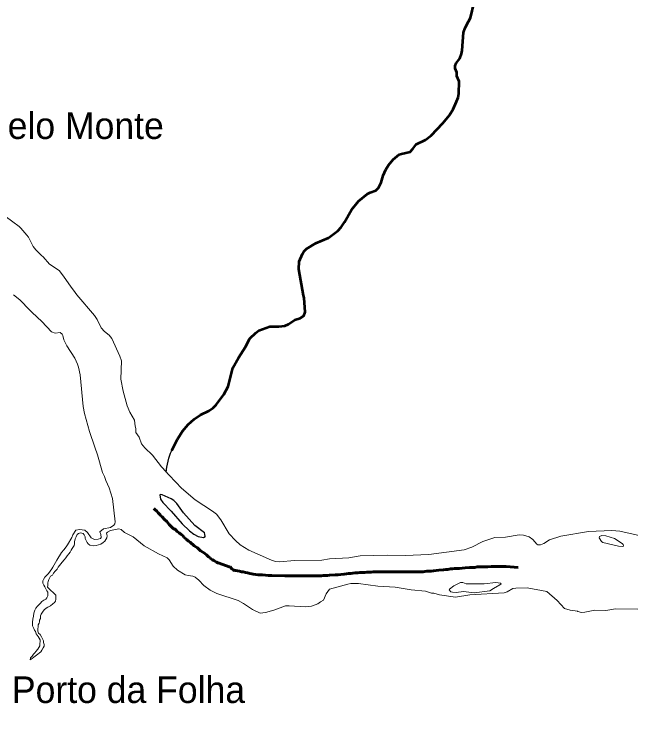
# Model space of a CAD drawing. Extents: x -1643653 to 4543381, y 1624270 to 13878484.
# Drawn here: x 689766 to 701363, y 8902478 to 8915829 of the extents above; entities that cross this region are included whole.
import ezdxf

# ---------------------------------------------------------------- set-up
doc = ezdxf.new("R2010")
doc.units = 0
doc.header["$LTSCALE"] = 200
doc.linetypes.add('LONG_DASH_SHORT_DASH', pattern=[9.9, 6, -1.2, 1.5, -1.2])
for name, color, linetype, lineweight in [('23', 7, 'Continuous', 13), ('24', 7, 'Continuous', 25), ('25', 7, 'Continuous', 13), ('60', 7, 'Continuous', 13), ('7', 7, 'LONG_DASH_SHORT_DASH', 60)]:
    doc.layers.add(name, color=color, linetype=linetype, lineweight=lineweight)
doc.layers.add('41', color=7, linetype='Continuous')

msp = doc.modelspace()

# ---------------------------------------------------------------- linework, layer by layer
at = {"layer": '23'}
for points in [[(689858, 8911832.1), (689622.7, 8912010.6), (689578.8, 8912037.9)], [(689858, 8911832.1), (689622.7, 8912010.6), (689578.8, 8912037.9)], [(690003.7, 8911671.2), (689891.4, 8911806.7), (689858, 8911832.1)], [(690003.7, 8911671.2), (689891.4, 8911806.7), (689858, 8911832.1)], [(690282.6, 8911287.6), (690170.1, 8911393.1), (690124.3, 8911459.3), (690036.2, 8911631.9), (690003.7, 8911671.2)], [(690282.6, 8911287.6), (690170.1, 8911393.1), (690124.3, 8911459.3), (690036.2, 8911631.9), (690003.7, 8911671.2)], [(690884, 8910634.6), (690838.4, 8910691.9), (690695.1, 8910901.9), (690608.8, 8911006.4), (690430.8, 8911126.3), (690310.1, 8911261.8), (690282.6, 8911287.6)], [(690884, 8910634.6), (690838.4, 8910691.9), (690695.1, 8910901.9), (690608.8, 8911006.4), (690430.8, 8911126.3), (690310.1, 8911261.8), (690282.6, 8911287.6)], [(692044.8, 8908056.7), (692038.9, 8908078.6), (692026.3, 8908188.9), (691941, 8908340.7), (691889.9, 8908460.7), (691815.3, 8908738.4), (691774.2, 8908959.6), (691782, 8909306.7), (691754.7, 8909393.1), (691600.1, 8909727.4), (691549.6, 8909789.6), (691461.9, 8909862.4), (691401.2, 8909927.1), (691329, 8910084.3), (691277.7, 8910162.7), (690943.9, 8910550.7), (690884, 8910634.6)], [(692044.8, 8908056.7), (692038.9, 8908078.6), (692026.3, 8908188.9), (691941, 8908340.7), (691889.9, 8908460.7), (691815.3, 8908738.4), (691774.2, 8908959.6), (691782, 8909306.7), (691754.7, 8909393.1), (691600.1, 8909727.4), (691549.6, 8909789.6), (691461.9, 8909862.4), (691401.2, 8909927.1), (691329, 8910084.3), (691277.7, 8910162.7), (690943.9, 8910550.7), (690884, 8910634.6)], [(692676.4, 8907162.1), (692551.5, 8907299.7), (692534.1, 8907312.8), (692364.9, 8907535.6), (692220.3, 8907669.3), (692160.1, 8907748.4), (692118.3, 8907868.3), (692050.7, 8907961), (692052.8, 8908026.7), (692044.8, 8908056.7)], [(692676.4, 8907162.1), (692551.5, 8907299.7), (692534.1, 8907312.8), (692364.9, 8907535.6), (692220.3, 8907669.3), (692160.1, 8907748.4), (692118.3, 8907868.3), (692050.7, 8907961), (692052.8, 8908026.7), (692044.8, 8908056.7)], [(699730.1, 8905870.1), (699662.2, 8905846.3), (699617, 8905846.3), (699595.2, 8905855.7), (699522.1, 8905946.6), (699449.5, 8905993.7), (699343.2, 8906026.8), (699263.6, 8906033.6), (699008.1, 8905992.8), (698805.8, 8905980.6), (698581.3, 8905906.7), (698370.6, 8905800.9), (698229, 8905748.8), (697567.1, 8905664.3), (697116.6, 8905647.9), (696786.4, 8905651), (696272.7, 8905636.6), (696059.6, 8905599.2), (695698.2, 8905581.4), (695553.9, 8905557.9), (695038, 8905553.4), (694755.6, 8905527.6), (694682.1, 8905531.8), (694607.4, 8905554.6), (694182.1, 8905744), (694016.8, 8905845.3), (693928.4, 8905925.4), (693809.1, 8906055.6), (693809.1, 8906055.6), (693650.4, 8906314.4), (693569.9, 8906419.6), (693492.8, 8906479), (693169.8, 8906693.4), (692915.7, 8906912.1), (692807.4, 8907022.5), (692676.4, 8907162.1)], [(699730.1, 8905870.1), (699662.2, 8905846.3), (699617, 8905846.3), (699595.2, 8905855.7), (699522.1, 8905946.6), (699449.5, 8905993.7), (699343.2, 8906026.8), (699263.6, 8906033.6), (699008.1, 8905992.8), (698805.8, 8905980.6), (698581.3, 8905906.7), (698370.6, 8905800.9), (698229, 8905748.8), (697567.1, 8905664.3), (697116.6, 8905647.9), (696786.4, 8905651), (696272.7, 8905636.6), (696059.6, 8905599.2), (695698.2, 8905581.4), (695553.9, 8905557.9), (695038, 8905553.4), (694755.6, 8905527.6), (694682.1, 8905531.8), (694607.4, 8905554.6), (694182.1, 8905744), (694016.8, 8905845.3), (693928.4, 8905925.4), (693809.1, 8906055.6), (693809.1, 8906055.6), (693650.4, 8906314.4), (693569.9, 8906419.6), (693492.8, 8906479), (693169.8, 8906693.4), (692915.7, 8906912.1), (692807.4, 8907022.5), (692676.4, 8907162.1)], [(703043.5, 8905742.3), (702942.6, 8905799.8), (702682, 8905912.8), (702436.8, 8905905.5), (702373, 8905910.6), (702175.9, 8905983.8), (702058.9, 8906003.4), (701803.5, 8905986.5), (701659.8, 8905992.8), (701154.5, 8906101.4), (701005.2, 8906113.6), (700564.9, 8906093.9), (700049.1, 8906011), (699833.6, 8905937.4), (699730.1, 8905870.1)], [(703043.5, 8905742.3), (702942.6, 8905799.8), (702682, 8905912.8), (702436.8, 8905905.5), (702373, 8905910.6), (702175.9, 8905983.8), (702058.9, 8906003.4), (701803.5, 8905986.5), (701659.8, 8905992.8), (701154.5, 8906101.4), (701005.2, 8906113.6), (700564.9, 8906093.9), (700049.1, 8906011), (699833.6, 8905937.4), (699730.1, 8905870.1)]]:
    msp.add_lwpolyline(points, dxfattribs=at)
at = {"layer": '24', "lineweight": 53}
for points in [[(698310.3, 8915692), (698345.2, 8915759.1), (698414.2, 8916049.1), (698434, 8916103.3), (698493.2, 8916205.4), (698541, 8916255.4), (698604.5, 8916300.2), (698689, 8916338.6), (698872.4, 8916392.4), (698958.8, 8916447.6), (698989, 8916484.6), (699031.1, 8916558.4), (699106, 8916749.2)], [(698089.5, 8914668.2), (698093, 8914730.9), (698057.9, 8914805.5), (698057.7, 8914860.2), (698080.5, 8914908.2), (698146.1, 8914998.1), (698179.3, 8915082.2), (698193.2, 8915143.2), (698213.4, 8915483.8), (698249.4, 8915574.9), (698249.4, 8915574.9), (698310.3, 8915692)], [(697317.1, 8913373.6), (697317.9, 8913374.9), (697500, 8913466.1), (697607.5, 8913547.4), (697828, 8913780.1), (697955.3, 8913931.9), (698021, 8914043.8), (698087.2, 8914183.8), (698114.2, 8914261.7), (698128.6, 8914336.6), (698136.1, 8914565.5), (698089.3, 8914664.5), (698089.5, 8914668.2)], [(695208.7, 8910534.7), (695119.1, 8911032.8), (695125.9, 8911175.9), (695186, 8911322.3), (695215, 8911364.1), (695265.4, 8911414.9), (695441.6, 8911520.3), (695675, 8911623.5), (695855.8, 8911754), (695917.1, 8911825.5), (695978.8, 8911914.3), (696107.7, 8912146.4), (696241.4, 8912314.4), (696408, 8912448.3), (696458.2, 8912475.5), (696564.9, 8912514.1), (696620.1, 8912562.5), (696669.6, 8912662.3), (696705.8, 8912792.2), (696757.7, 8912906), (696806.1, 8912989), (696891.2, 8913095.4), (697004, 8913188.5), (697047.8, 8913204.1), (697212.1, 8913236.8), (697263.3, 8913295.3), (697317.1, 8913373.6)], [(692729.3, 8907617.7), (692837, 8907833), (692931.9, 8907984.6), (693036.8, 8908107.6), (693151.9, 8908211.5), (693272.4, 8908290), (693424.2, 8908367.8), (693510.8, 8908421.2), (693567.8, 8908481.1), (693707.6, 8908675), (693789, 8908827.4), (693880.7, 8909177.6), (693984.3, 8909363.3), (694118.8, 8909572.9), (694196.2, 8909725.9), (694310.5, 8909836.8), (694368.1, 8909876.1), (694574.8, 8909952.9), (694743.6, 8909954), (694858.1, 8909968.9), (694926.1, 8910000.5), (695042.3, 8910075.9), (695142.1, 8910109.8), (695197.6, 8910138.8), (695213.4, 8910155.1), (695235.8, 8910220.2), (695216.8, 8910490.1), (695208.7, 8910534.7)]]:
    msp.add_lwpolyline(points, dxfattribs=at)
at = {"layer": '24'}
for points in [[(698310.3, 8915692), (698345.2, 8915759.1), (698414.2, 8916049.1), (698434, 8916103.3), (698493.2, 8916205.4), (698541, 8916255.4), (698604.5, 8916300.2), (698689, 8916338.6), (698872.4, 8916392.4), (698958.8, 8916447.6), (698989, 8916484.6), (699031.1, 8916558.4), (699106, 8916749.2)], [(698089.5, 8914668.2), (698093, 8914730.9), (698057.9, 8914805.5), (698057.7, 8914860.2), (698080.5, 8914908.2), (698146.1, 8914998.1), (698179.3, 8915082.2), (698193.2, 8915143.2), (698213.4, 8915483.8), (698249.4, 8915574.9), (698249.4, 8915574.9), (698310.3, 8915692)], [(697317.1, 8913373.6), (697317.9, 8913374.9), (697500, 8913466.1), (697607.5, 8913547.4), (697828, 8913780.1), (697955.3, 8913931.9), (698021, 8914043.8), (698087.2, 8914183.8), (698114.2, 8914261.7), (698128.6, 8914336.6), (698136.1, 8914565.5), (698089.3, 8914664.5), (698089.5, 8914668.2)], [(695208.7, 8910534.7), (695119.1, 8911032.8), (695125.9, 8911175.9), (695186, 8911322.3), (695215, 8911364.1), (695265.4, 8911414.9), (695441.6, 8911520.3), (695675, 8911623.5), (695855.8, 8911754), (695917.1, 8911825.5), (695978.8, 8911914.3), (696107.7, 8912146.4), (696241.4, 8912314.4), (696408, 8912448.3), (696458.2, 8912475.5), (696564.9, 8912514.1), (696620.1, 8912562.5), (696669.6, 8912662.3), (696705.8, 8912792.2), (696757.7, 8912906), (696806.1, 8912989), (696891.2, 8913095.4), (697004, 8913188.5), (697047.8, 8913204.1), (697212.1, 8913236.8), (697263.3, 8913295.3), (697317.1, 8913373.6)], [(692627.4, 8907216), (692639.9, 8907309.9), (692674.3, 8907477.3), (692707.2, 8907573.5), (692837, 8907833), (692931.9, 8907984.6), (693036.8, 8908107.6), (693151.9, 8908211.5), (693272.4, 8908290), (693424.2, 8908367.8), (693510.8, 8908421.2), (693567.8, 8908481.1), (693707.6, 8908675), (693789, 8908827.4), (693880.7, 8909177.6), (693984.3, 8909363.3), (694118.8, 8909572.9), (694196.2, 8909725.9), (694310.5, 8909836.8), (694368.1, 8909876.1), (694574.8, 8909952.9), (694743.6, 8909954), (694858.1, 8909968.9), (694926.1, 8910000.5), (695042.3, 8910075.9), (695142.1, 8910109.8), (695197.6, 8910138.8), (695213.4, 8910155.1), (695235.8, 8910220.2), (695216.8, 8910490.1), (695208.7, 8910534.7)]]:
    msp.add_lwpolyline(points, dxfattribs=at)
msp.add_lwpolyline([(692949.1, 8906444.8), (692825.9, 8906621.7), (692768.5, 8906681.2), (692716.6, 8906713.2), (692549.3, 8906785.2), (692516.7, 8906791.5), (692502.1, 8906785.4), (692518.4, 8906705.4), (692562.6, 8906642), (692720.7, 8906481.3), (692924.1, 8906239.9), (693063.6, 8906110.7), (693147.4, 8906045), (693227.3, 8906002.2), (693327.7, 8905986.2), (693357, 8906001.2), (693353.1, 8906048.7), (693342.8, 8906070), (693166.4, 8906209.1)], close=True, dxfattribs=at)
at = {"layer": '25'}
for points in [[(689578.8, 8912037.9), (689622.7, 8912010.6), (689858, 8911832.1)], [(689858, 8911832.1), (689891.4, 8911806.7), (690003.7, 8911671.2)], [(690003.7, 8911671.2), (690036.2, 8911631.9), (690124.3, 8911459.3), (690170.1, 8911393.1), (690282.6, 8911287.6)], [(690282.6, 8911287.6), (690310.1, 8911261.8), (690430.8, 8911126.3), (690608.8, 8911006.4), (690695.1, 8910901.9), (690838.4, 8910691.9), (690884, 8910634.6)], [(690884, 8910634.6), (690943.9, 8910550.7), (691277.7, 8910162.7), (691329, 8910084.3), (691401.2, 8909927.1), (691461.9, 8909862.4), (691549.6, 8909789.6), (691600.1, 8909727.4), (691754.7, 8909393.1), (691782, 8909306.7), (691774.2, 8908959.6), (691815.3, 8908738.4), (691889.9, 8908460.7), (691941, 8908340.7), (692026.3, 8908188.9), (692038.9, 8908078.6), (692044.8, 8908056.7)], [(690105.8, 8910215.6), (690059.9, 8910258.2), (689871, 8910454.6), (689754.4, 8910550.3)], [(690973.8, 8909186.5), (690959.4, 8909246.9), (690907.6, 8909357.3), (690755.8, 8909591), (690701.9, 8909701.7), (690681.3, 8909786.2), (690666.4, 8909810.3), (690629.5, 8909837.9), (690534.7, 8909826.2), (690465.2, 8909853.3), (690285, 8910049.6), (690105.8, 8910215.6)], [(691088.5, 8908313.9), (691062.8, 8908449.1), (691008.4, 8909041.9), (690973.8, 8909186.5)], [(691281.4, 8907685.4), (691182.4, 8907975.5), (691088.5, 8908313.9)], [(692044.8, 8908056.7), (692052.8, 8908026.7), (692050.7, 8907961), (692118.3, 8907868.3), (692160.1, 8907748.4), (692220.3, 8907669.3), (692364.9, 8907535.6), (692534.1, 8907312.8), (692551.5, 8907299.7), (692676.4, 8907162.1)], [(691462.3, 8907129.9), (691427, 8907209), (691331.2, 8907539.4), (691281.4, 8907685.4)], [(690770.2, 8905843.2), (690852, 8905982.1), (690868.1, 8906034.4), (690928, 8906123.4), (690992.1, 8906133.5), (691093.1, 8906124.6), (691142.8, 8906079.2), (691216.8, 8905979), (691277.6, 8905948.2), (691342.5, 8905951.8), (691386.5, 8905966.2), (691399.8, 8905981.8), (691397.7, 8906042.2), (691378.7, 8906092.7), (691448.3, 8906144.9), (691574.6, 8906171.9), (691637.5, 8906214.2), (691659.8, 8906239.5), (691666.5, 8906276.9), (691614.3, 8906720.4), (691553.2, 8906917.7), (691488.1, 8907058.8), (691462.3, 8907129.9)], [(692676.4, 8907162.1), (692807.4, 8907022.5), (692915.7, 8906912.1), (693169.8, 8906693.4), (693492.8, 8906479), (693569.9, 8906419.6), (693650.4, 8906314.4), (693809.1, 8906055.6), (693809.1, 8906055.6), (693928.4, 8905925.4), (694016.8, 8905845.3), (694182.1, 8905744), (694607.4, 8905554.6), (694682.1, 8905531.8), (694755.6, 8905527.6), (695038, 8905553.4), (695553.9, 8905557.9), (695698.2, 8905581.4), (696059.6, 8905599.2), (696272.7, 8905636.6), (696786.4, 8905651), (697116.6, 8905647.9), (697567.1, 8905664.3), (698229, 8905748.8), (698370.6, 8905800.9), (698581.3, 8905906.7), (698805.8, 8905980.6), (699008.1, 8905992.8), (699263.6, 8906033.6), (699343.2, 8906026.8), (699449.5, 8905993.7), (699522.1, 8905946.6), (699595.2, 8905855.7), (699617, 8905846.3), (699662.2, 8905846.3), (699730.1, 8905870.1)], [(691259.2, 8905826.4), (691259.2, 8905826.4), (691190.1, 8905839.8), (691158.9, 8905862.1), (691141.1, 8905891), (691121, 8905926.7), (691103.2, 8905962.3), (691098.7, 8905998), (691080.9, 8906031.4), (691063.1, 8906058.1), (691014, 8906069.2), (691014, 8906069.2), (690976.2, 8906058.1), (690976.2, 8906058.1), (690950.8, 8906042.4), (690932.7, 8905999.2), (690914.6, 8905958.6), (690901.5, 8905902.7), (690898.7, 8905862), (690893.5, 8905831.5), (690857.5, 8905778.3), (690836.9, 8905745.3), (690816.3, 8905709.8), (690790.7, 8905676.9), (690759.9, 8905638.9), (690736.8, 8905603.4), (690706, 8905562.8), (690670.1, 8905517.2), (690641.9, 8905486.9), (690618.8, 8905459), (690595.7, 8905428.6), (690575.1, 8905388), (690536.7, 8905350.1), (690503.4, 8905312.1), (690485.4, 8905276.6), (690449.6, 8905256.4), (690436.7, 8905228.5), (690418.7, 8905190.4), (690405.7, 8905157.4), (690397.9, 8905129.5), (690397.6, 8905081.1), (690392.3, 8905048.1), (690422.7, 8905017.4), (690453, 8904989.3), (690498.6, 8904945.8), (690526.4, 8904922.7), (690546.6, 8904897.2), (690546.1, 8904820.8), (690543.3, 8904787.8), (690525.4, 8904759.9), (690492.1, 8904737.2), (690446.1, 8904699.3), (690400.1, 8904671.6), (690366.9, 8904653.9), (690328.6, 8904623.6), (690300.3, 8904580.5), (690274.6, 8904539.9), (690261.7, 8904512), (690258.8, 8904461.2), (690240.8, 8904428.2), (690240.6, 8904397.7), (690232.8, 8904369.7), (690214.8, 8904339.3), (690214.6, 8904308.8), (690211.8, 8904260.4), (690211.5, 8904219.8), (690221.5, 8904181.5), (690251.8, 8904155.9), (690282.1, 8904117.6), (690297.2, 8904079.4), (690317.2, 8904038.6), (690319.6, 8904010.6), (690327, 8903972.4), (690326.8, 8903941.8), (690311.3, 8903908.9), (690288.2, 8903863.2), (690267.6, 8903835.3), (690239.5, 8903812.6), (690211.3, 8903787.3), (690183.2, 8903767.1), (690134.7, 8903731.8), (690106.5, 8903709), (690068.2, 8903683.8), (690073.5, 8903719.4), (690106.8, 8903752.2), (690129.9, 8903787.7), (690155.5, 8903813), (690176.1, 8903840.9), (690211.9, 8903881.4), (690230, 8903916.9), (690248, 8903947.4), (690250.8, 8903988), (690256.1, 8904026.2), (690256.3, 8904059.2), (690236.2, 8904089.9), (690218.5, 8904118), (690195.8, 8904146.1), (690180.7, 8904174.1), (690165.7, 8904212.4), (690148.1, 8904243), (690133, 8904273.6)], [(691574.8, 8906114.8), (691519.4, 8906081.7), (691502.8, 8906063.3), (691513.3, 8906012.8), (691511.5, 8905978.9), (691473.5, 8905914.1), (691441.2, 8905891.3)], [(694392.3, 8904560.9), (694249.3, 8904629.2), (694079.7, 8904743.6), (693976.2, 8904798), (693575.7, 8904930.8), (693449.1, 8904994.9), (693335.6, 8905079), (693236.3, 8905180.3), (693168.5, 8905236.3), (693127.6, 8905254.1), (693035.4, 8905267.9), (692983.1, 8905283.9), (692837.7, 8905367.1), (692753.6, 8905443.3), (692681.2, 8905561), (692642.1, 8905601), (692477.9, 8905674), (692207.4, 8905825.7), (692006.3, 8905995.8), (691843, 8906078.6), (691777.9, 8906135.4), (691733.2, 8906147.2), (691574.8, 8906114.8)], [(699730.1, 8905870.1), (699833.6, 8905937.4), (700049.1, 8906011), (700564.9, 8906093.9), (701005.2, 8906113.6), (701154.5, 8906101.4), (701659.8, 8905992.8), (701803.5, 8905986.5), (702058.9, 8906003.4), (702175.9, 8905983.8), (702373, 8905910.6), (702436.8, 8905905.5), (702682, 8905912.8), (702942.6, 8905799.8), (703043.5, 8905742.3)], [(690133, 8904273.6), (690112.9, 8904319.5), (690113.4, 8904393.3), (690118.8, 8904446.7), (690131.9, 8904502.6), (690134.8, 8904558.5), (690153, 8904614.4), (690171, 8904655), (690204.3, 8904690.4), (690235.1, 8904723.3), (690260.7, 8904751.2), (690283.8, 8904779), (690322.1, 8904801.7), (690360.4, 8904821.8), (690378.3, 8904849.7), (690396.4, 8904887.8), (690396.8, 8904953.9), (690381.7, 8904982), (690361.6, 8905017.7), (690341.5, 8905058.6), (690323.9, 8905086.6), (690306.3, 8905127.4), (690306.6, 8905168.1), (690314.4, 8905193.5), (690340.1, 8905236.6), (690373.4, 8905267), (690409.2, 8905307.5), (690440, 8905348), (690475.9, 8905391.1), (690494, 8905426.6), (690519.7, 8905469.7), (690566, 8905556), (690657.5, 8905699.5), (690657.5, 8905699.5), (690702.1, 8905750.7), (690702.1, 8905750.7), (690746.6, 8905810.9), (690770.2, 8905843.2)], [(691441.2, 8905891.3), (691395.3, 8905858.9), (691308.5, 8905834.7), (691259.2, 8905826.4)], [(697658.8, 8904933.3), (697614.4, 8904938.5), (697502.5, 8904976.8), (697230.9, 8904997.9), (696928.2, 8905046.6), (696603.4, 8905069), (696240.1, 8905118.1), (696100.1, 8905116.6), (696040.6, 8905107), (695698.7, 8905008.5), (695631.9, 8904924.3), (695580.3, 8904801.6), (695529.7, 8904770.2)], [(700224.1, 8904617.8), (700117.5, 8904650.2), (699976.3, 8904795.3), (699784.6, 8904967), (699413.2, 8905038.8), (699203.8, 8905030.7), (699146, 8905026.8), (699035.3, 8904960.2), (698980, 8904944.5), (698337.8, 8904907.7), (698063.3, 8904859.2), (697765.1, 8904905.4), (697658.8, 8904933.3)], [(695529.7, 8904770.2), (695479.1, 8904738.8), (695358.2, 8904694.2), (695244.6, 8904680.4), (694936.5, 8904701), (694868.4, 8904699.3), (694652.2, 8904617.7), (694490.8, 8904574.4), (694392.3, 8904560.9)], [(700368.5, 8904593.8), (700361.3, 8904595.9), (700224.1, 8904617.8)], [(701498, 8904635.9), (701073.3, 8904639.9), (700893.6, 8904612.2), (700683.7, 8904613.8), (700499, 8904578.5), (700435.5, 8904574.2), (700368.5, 8904593.8)]]:
    msp.add_lwpolyline(points, dxfattribs=at)
for points in [[(692949.1, 8906444.8), (692825.9, 8906621.7), (692768.5, 8906681.2), (692716.6, 8906713.2), (692549.3, 8906785.2), (692516.7, 8906791.5), (692502.1, 8906785.4), (692518.4, 8906705.4), (692562.6, 8906642), (692720.7, 8906481.3), (692924.1, 8906239.9), (693063.6, 8906110.7), (693147.4, 8906045), (693227.3, 8906002.2), (693327.7, 8905986.2), (693357, 8906001.2), (693353.1, 8906048.7), (693342.8, 8906070), (693166.4, 8906209.1)], [(700838.5, 8905891.3), (701132.3, 8905819.6), (701206.6, 8905813.1), (701222.7, 8905818.2), (701228.3, 8905829.3), (701220.6, 8905851.5), (701199.7, 8905872.4), (701053.6, 8905962.1), (700895.4, 8906014.9), (700818.6, 8906021.5), (700774.5, 8906004.3), (700770.3, 8905978.1), (700810.1, 8905908.9)], [(698388.1, 8905109.3), (698266.4, 8905115), (698201.6, 8905136.8), (698161, 8905135.9), (698032.8, 8905076.5), (697953.2, 8905013.6), (697944, 8904996.2), (697979.2, 8904962.2), (698006.7, 8904952.9), (698079.2, 8904948.8), (698215.6, 8904965.4), (698416.1, 8904942.8), (698710.2, 8904978.5), (698778.6, 8905025.1), (698900.2, 8905090.5), (698922.8, 8905112.6), (698909.9, 8905123.1), (698826.8, 8905137.9), (698603.2, 8905114.8)]]:
    msp.add_lwpolyline(points, close=True, dxfattribs=at)
at = {"layer": '60', "lineweight": 25}
msp.add_spline([(814781, 9009175.5), (814787.2, 9009173.4), (814796.9, 9009173.4), (814799.4, 9009172.4), (814805.1, 9009174.5), (814805.6, 9009176.5), (814811.7, 9009179.5), (814811.7, 9009179.5), (814801.5, 9009181), (814790.7, 9009181.5), (814784.1, 9009183.1), (814777.4, 9009185.1), (814778.4, 9009175.5)], degree=3, dxfattribs=at)
at = {"layer": '7'}
for points in [[(693130.7, 8905846.2), (693095, 8905876.9), (693074.7, 8905894.8), (693044.1, 8905912.6), (693023.8, 8905933.1), (693000.9, 8905948.4), (692983.1, 8905968.9), (692955.1, 8905989.3), (692934.7, 8906022.6), (692904.1, 8906037.9), (692871.1, 8906073.7), (692830.3, 8906094.1), (692797.2, 8906132.5), (692754, 8906155.5), (692713.2, 8906198.9), (692680.2, 8906229.6), (692634.3, 8906283.3), (692593.6, 8906324.2), (692550.3, 8906370.2), (692522.3, 8906390.6), (692509.6, 8906411.1), (692476.5, 8906446.9), (692448.5, 8906480.1), (692412.9, 8906510.8), (692392.5, 8906531.2)], [(694492.2, 8905273.6), (694436.2, 8905278.7), (694392.9, 8905278.7), (694352.2, 8905281.3), (694260.6, 8905294.1), (694235.2, 8905299.2), (694197, 8905306.9), (694176.7, 8905314.5), (694151.2, 8905319.6), (694115.6, 8905327.3), (694074.9, 8905335), (694044.3, 8905340.1), (694003.6, 8905347.8), (693965.4, 8905355.4), (693932.4, 8905360.5), (693912, 8905363.1), (693881.5, 8905373.3), (693861.1, 8905391.2), (693830.6, 8905429.6), (693810.2, 8905432.1), (693619.3, 8905498.6), (693596.4, 8905508.8), (693573.5, 8905521.6), (693553.2, 8905534.3), (693522.6, 8905552.2), (693494.6, 8905562.5), (693466.6, 8905580.3), (693448.8, 8905600.8), (693418.3, 8905618.7), (693382.7, 8905654.5), (693349.6, 8905685.2), (693324.1, 8905700.5), (693270.7, 8905733.7), (693240.1, 8905766.9), (693212.1, 8905787.4), (693153.6, 8905828.3), (693130.7, 8905846.2)], [(699241.8, 8905417.5), (699018.7, 8905439.9), (698972.9, 8905439.9), (698924.6, 8905439.9), (698871.2, 8905439.9), (698799.9, 8905439.9), (698733.8, 8905439.9), (698675.2, 8905434.8), (698609.1, 8905432.2), (698563.3, 8905432.2), (698520, 8905429.6), (698474.2, 8905429.6), (698431, 8905422), (698387.7, 8905422), (698331.7, 8905419.4), (698247.8, 8905411.7), (698191.8, 8905409.2), (698140.9, 8905401.5), (698092.6, 8905401.5), (698049.3, 8905399), (698008.6, 8905391.3), (697970.4, 8905391.3), (697922.1, 8905383.6), (697886.5, 8905383.6), (697843.2, 8905378.5), (697754.2, 8905368.3), (697700.7, 8905363.2), (697649.8, 8905358.1), (697609.1, 8905352.9), (697565.9, 8905350.4)], [(697565.9, 8905350.4), (697527.7, 8905347.8), (697489.5, 8905342.7), (697456.5, 8905340.2), (697420.8, 8905337.6), (697380.1, 8905335), (697336.9, 8905335), (697280.9, 8905335), (697230, 8905335), (697186.8, 8905335), (697148.6, 8905335), (697105.3, 8905335), (697082.4, 8905335), (697046.8, 8905335), (697011.2, 8905335), (696990.8, 8905335), (696957.7, 8905335), (696934.8, 8905335), (696896.7, 8905335), (696876.3, 8905335), (696820.3, 8905335), (696772, 8905335), (696721.1, 8905335), (696670.2, 8905335), (696624.4, 8905335), (696578.6, 8905335), (696520.1, 8905335), (696481.9, 8905332.5), (696438.7, 8905332.5), (696398, 8905329.9), (696359.8, 8905327.3), (696314, 8905324.8), (696265.7, 8905322.2), (696227.5, 8905319.7), (696176.6, 8905317.1), (696135.9, 8905312), (696095.2, 8905306.9), (696054.5, 8905304.3), (696013.8, 8905299.2), (695970.5, 8905294.1), (695906.9, 8905289), (695858.6, 8905283.9), (695800, 8905281.3), (695698.3, 8905273.7), (695657.6, 8905271.1), (695616.8, 8905268.5), (695578.7, 8905268.5), (695548.1, 8905263.4), (695510, 8905260.9), (695464.2, 8905260.9), (695426, 8905260.9), (695377.7, 8905260.9), (695339.5, 8905260.9), (695293.7, 8905260.9), (695242.8, 8905260.9), (695194.5, 8905260.9), (695143.6, 8905260.9), (695097.8, 8905260.9), (695052, 8905260.9), (695001.1, 8905260.9), (694945.1, 8905260.9), (694856, 8905263.4), (694614.3, 8905268.5), (694545.6, 8905271.1), (694492.2, 8905273.6)]]:
    msp.add_lwpolyline(points, dxfattribs=at)

# ---------------------------------------------------------------- texts
at = {"layer": '41'}
for s, p in [('Belo Monte', (689197.5, 8913481.5)), ('Porto da Folha', (689722.9, 8902870))]:
    msp.add_text(s, height=500, dxfattribs=at).set_placement(p)

doc.saveas('drawing.dxf')
